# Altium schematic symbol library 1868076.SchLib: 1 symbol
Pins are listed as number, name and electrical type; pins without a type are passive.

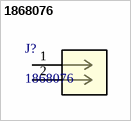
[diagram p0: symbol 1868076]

## 1868076
designator J?
PCB terminal block, nominal current: 32 A, nom. voltage: 630 V, pitch: 7.62 mm, number of positions: 2, connection method: Screw connection with tension sleeve, mounting: Wave soldering, conductor/PCB connection direction: 0 Â°, color: green. The article can be aligned to create different nos. of positions!; Manufacturer_Name: Phoenix Contact
footprint CONN_1868076_PXC
pins: 1, 2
